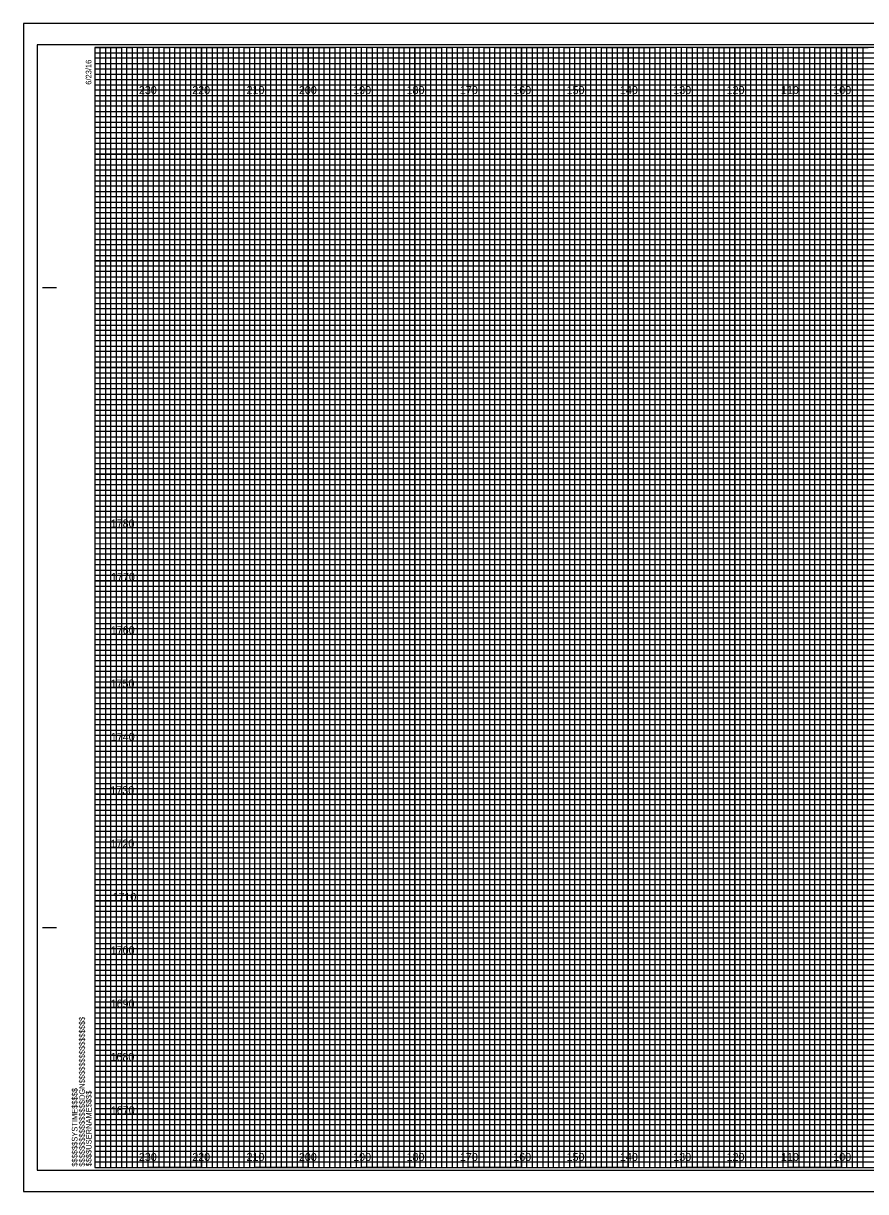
# Model space of a CAD drawing. Extents: x -419 to 4739, y -630 to 13534.
# Drawn here: x 3347.7 to 3505.6, y -29.6 to 189.4 of the extents above; entities that cross this region are included whole.
import ezdxf

# ---------------------------------------------------------------- set-up
doc = ezdxf.new("R2010")
doc.units = 0
for name, color, linetype in [('Old_Level_62', 7, 'Continuous'), ('Pattern 1', 7, 'Continuous'), ('Pattern 18', 7, 'Continuous'), ('Pattern 4', 7, 'Continuous'), ('Pattern 5', 7, 'Continuous'), ('Prop Dimension', 7, 'Continuous'), ('Prop Horizontal Alignment', 7, 'Continuous'), ('Raster_Level_0', 7, 'Continuous'), ('Scratch_Level_0', 7, 'Continuous'), ('Scratch_Level_3', 7, 'Continuous'), ('Scratch_Level_5', 7, 'Continuous')]:
    doc.layers.add(name, color=color, linetype=linetype)

msp = doc.modelspace()

# ---------------------------------------------------------------- linework, layer by layer
at = {"layer": 'Old_Level_62'}
for p, q in [((3351.3, 139.94), (3353.8, 139.94)), ((3351.4, 139.94), (3353.9, 139.94)), ((3351.3, 19.94), (3353.8, 19.94)), ((3351.4, 19.94), (3353.9, 19.94)), ((3361.1, -25.06), (3361.1, -25.06)), ((3361.1, -25.06), (3361.1, -25.06)), ((3361.1, -25.06), (3361.1, -25.06)), ((3361.1, -25.06), (3361.1, -25.06)), ((3361.1, -25.06), (3361.1, -25.06)), ((3361.1, -25.06), (3361.1, -25.06)), ((3361.1, -25.06), (3361.1, -25.06))]:
    msp.add_line(p, q, dxfattribs=at)
msp.add_lwpolyline([(3681.1, 184.94), (3361.1, 184.94), (3361.1, -25.06), (3681.1, -25.06)], close=True, dxfattribs=at)
at = {"layer": 'Pattern 18'}
msp.add_lwpolyline([(3347.7, -29.56), (3684.4, -29.56), (3684.4, 189.44), (3347.7, 189.44)], close=True, dxfattribs=at)
at = {"layer": 'Pattern 4'}
for p, q in [((3361.1, 183.94), (3621.1, 183.94)), ((3621.1, 182.92), (3361.1, 182.92)), ((3361.1, 182.92), (3361.1, 181.94)), ((3361.1, 181.94), (3621.1, 181.94)), ((3621.1, 180.83), (3361.1, 180.83)), ((3361.1, 180.83), (3361.1, 178.94)), ((3361.1, 178.94), (3681.1, 178.94))]:
    msp.add_line(p, q, dxfattribs=at)
for points in [[(3361.1, 177.94), (3631.1, 177.94), (3681.1, 177.94), (3681.1, 176.94), (3361.1, 176.94)], [(3361.1, 175.94), (3681.1, 175.94), (3681.1, 173.94), (3361.1, 173.94)], [(3361.1, 172.94), (3681.1, 172.94), (3681.1, 171.94), (3361.1, 171.92)], [(3361.1, 170.94), (3681.1, 170.94), (3681.1, 168.94), (3361.1, 168.94)], [(3361.1, 167.94), (3681.1, 167.94), (3681.1, 166.94), (3361.1, 166.94)], [(3361.1, 165.94), (3681.1, 165.94), (3681.1, 163.94), (3361.1, 163.94)], [(3361.1, 162.94), (3681.1, 162.94), (3681.1, 161.94), (3361.1, 161.94)], [(3361.1, 160.94), (3681.1, 160.94), (3681.1, 158.94), (3361.1, 158.94)], [(3361.1, 157.94), (3681.1, 157.94), (3681.1, 156.94), (3361.1, 156.94)], [(3361.1, 155.94), (3681.1, 155.94), (3681.1, 153.94), (3361.1, 153.94)], [(3361.1, 152.94), (3681.1, 152.94), (3681.1, 151.94), (3361.1, 151.94)], [(3361.1, 150.94), (3681.1, 150.94), (3681.1, 148.89), (3681.1, 147.94), (3681.1, 146.94), (3361.1, 146.94)], [(3361.1, 148.94), (3681.1, 148.94), (3681.1, 147.94), (3361.1, 147.94)], [(3361.1, 145.94), (3681.1, 145.94), (3681.1, 143.94), (3361.1, 143.97)], [(3361.1, 143.97), (3681.1, 143.94), (3681.1, 142.94), (3361.1, 142.94)], [(3361.1, 141.94), (3681.1, 141.94), (3681.1, 140.94), (3361.1, 140.94)], [(3361.1, 138.94), (3681.1, 138.94), (3681.1, 137.94), (3361.1, 137.94)], [(3361.1, 136.94), (3681.1, 136.94), (3681.1, 135.94), (3361.1, 135.94)], [(3361.03, 133.83), (3681.1, 133.83), (3681.1, 132.82), (3361.03, 132.82)], [(3361.1, 131.94), (3681.1, 131.94), (3681.1, 130.94), (3361.1, 130.94)], [(3361.1, 128.94), (3681.1, 128.94), (3681.1, 127.94), (3361.1, 127.94)], [(3361.1, 126.94), (3681.1, 126.94), (3681.1, 125.94), (3361.1, 125.94)], [(3361.1, 123.94), (3681.1, 123.94), (3681.1, 122.94), (3361.1, 122.94)], [(3361.1, 121.94), (3681.1, 121.94), (3681.1, 120.94), (3361.1, 120.94)], [(3361.1, 118.94), (3681.1, 118.94), (3681.1, 117.94), (3361.1, 117.94)], [(3361.1, 116.94), (3681.1, 116.94), (3681.1, 115.94), (3361.1, 115.94)], [(3361.1, 113.94), (3681.1, 113.94), (3681.09, 112.92), (3361.1, 112.94)], [(3361.1, 111.94), (3681.1, 111.94), (3681.1, 110.94), (3361.1, 110.94)], [(3361.1, 108.94), (3681.1, 108.94), (3681.1, 107.94), (3361.1, 107.94)], [(3361.1, 106.94), (3681.1, 106.94), (3681.1, 105.94), (3361.1, 105.94)], [(3361.1, 103.94), (3681.1, 103.94), (3681.1, 102.94), (3361.1, 102.94)], [(3361.1, 101.94), (3681.1, 101.94), (3681.1, 100.94), (3361.1, 100.94)], [(3361.1, 98.94), (3681.1, 98.94), (3681.1, 97.94), (3361.1, 97.94)], [(3361.1, 96.94), (3681.1, 96.94), (3681.1, 95.94), (3361.1, 95.94)], [(3361.1, 93.94), (3681.1, 93.94), (3681.1, 92.94), (3361.1, 92.94)], [(3361.1, 91.93), (3681.17, 91.85), (3681.1, 90.94), (3361.1, 90.94)], [(3361.1, 88.94), (3681.1, 88.94), (3681.1, 87.94), (3361.1, 87.94)], [(3361.1, 86.94), (3681.1, 86.94), (3681.1, 85.94), (3361.1, 85.94)], [(3361.1, 83.94), (3681.1, 83.94), (3681.1, 82.94), (3361.1, 82.94)], [(3361.1, 81.94), (3681.1, 81.94), (3681.1, 80.94), (3361.1, 80.94)], [(3361.1, 78.94), (3681.1, 78.94), (3681.1, 77.94), (3361.1, 77.94)], [(3361.1, 76.94), (3681.1, 76.94), (3681.1, 75.94), (3361.1, 75.94)], [(3361.1, 73.94), (3681.1, 73.94), (3681.1, 72.94), (3361.1, 72.94)], [(3361.1, 71.94), (3681.1, 71.94), (3681.1, 70.94), (3361.1, 70.94)], [(3361.1, 68.94), (3681.1, 68.94), (3681.1, 67.94), (3361.1, 67.94)], [(3361.1, 66.94), (3681.1, 66.94), (3681.1, 65.94), (3361.1, 65.94)], [(3361.1, 63.94), (3681.1, 63.94), (3681.1, 62.94), (3361.1, 62.94)], [(3361.1, 61.94), (3681.1, 61.94), (3681.1, 60.94), (3361.1, 60.94)], [(3361.1, 58.94), (3681.1, 58.94), (3681.1, 57.94), (3361.1, 57.94)], [(3361.1, 56.94), (3681.1, 56.94), (3681.1, 55.94), (3361.1, 55.94)], [(3361.1, 53.94), (3681.1, 53.94), (3681.09, 52.92), (3361.1, 52.94)], [(3361.1, 51.94), (3681.1, 51.94), (3681.1, 50.94), (3361.1, 50.94)], [(3361.1, 48.94), (3681.1, 48.94), (3681.1, 47.94), (3361.1, 47.94)], [(3361.1, 46.94), (3681.1, 46.94), (3681.1, 45.94), (3361.1, 45.94)], [(3361.1, 43.94), (3681.1, 43.94), (3681.1, 42.94), (3361.1, 42.94)], [(3361.1, 41.94), (3681.1, 41.94), (3681.1, 40.94), (3361.1, 40.94)], [(3361.1, 38.94), (3681.1, 38.94), (3681.1, 37.94), (3361.1, 37.94)], [(3361.1, 36.94), (3681.1, 36.94), (3681.1, 35.94), (3361.1, 35.94)], [(3361.1, 33.94), (3681.1, 33.94), (3681.1, 32.94), (3361.1, 32.94)], [(3361.1, 31.93), (3681.17, 31.85), (3681.1, 30.94), (3361.1, 30.94)], [(3361.1, 28.94), (3681.1, 28.94), (3681.1, 27.94), (3361.1, 27.94)], [(3361.1, 26.94), (3681.1, 26.94), (3681.1, 25.94), (3361.1, 25.94)], [(3361.1, 23.94), (3681.1, 23.94), (3681.1, 22.94), (3361.1, 22.94)], [(3361.1, 21.94), (3681.1, 21.94), (3681.1, 20.94), (3361.1, 20.94)], [(3361.1, 18.94), (3681.1, 18.94), (3681.1, 17.94), (3361.1, 17.94)], [(3361.1, 16.94), (3681.1, 16.94), (3681.1, 15.94), (3361.1, 15.94)], [(3361.1, 13.94), (3681.1, 13.94), (3681.1, 12.94), (3361.1, 12.94)], [(3361.1, 11.94), (3681.1, 11.94), (3681.1, 10.94), (3361.1, 10.94)], [(3361.1, 8.94), (3681.1, 8.94), (3681.1, 7.94), (3361.1, 7.94)], [(3361.1, 6.94), (3681.1, 6.94), (3681.1, 5.94), (3361.1, 5.94)], [(3361.1, 3.94), (3681.1, 3.94), (3681.1, 2.94), (3361.1, 2.94)], [(3361.1, 1.94), (3681.1, 1.94), (3681.1, 0.94), (3361.1, 0.94)], [(3361.1, -1.06), (3681.1, -1.06), (3681.1, -2.06), (3361.1, -2.06)], [(3361.1, -3.06), (3681.1, -3.06), (3681.1, -4.06), (3361.1, -4.06)], [(3361.1, -6.06), (3681.1, -6.06), (3681.1, -7.06), (3361.1, -7.06)], [(3361.1, -8.06), (3681.1, -8.06), (3681.1, -9.06), (3361.1, -9.06)], [(3361.1, -11.06), (3681.1, -11.06), (3681.1, -12.06), (3361.1, -12.06)], [(3361.1, -13.06), (3681.1, -13.06), (3681.1, -14.06), (3361.1, -14.06)], [(3361.1, -16.06), (3681.1, -16.06), (3681.1, -17.06), (3361.1, -17.06)], [(3361.1, -18.06), (3681.1, -18.06), (3681.1, -19.06), (3361.1, -19.06)], [(3361.1, -21.06), (3681.1, -21.06), (3681.1, -22.06), (3361.1, -22.06)], [(3361.1, -23.06), (3681.1, -23.06), (3681.1, -24.06), (3361.1, -24.06)]]:
    msp.add_lwpolyline(points, dxfattribs=at)
at = {"layer": 'Pattern 5'}
for p, q in [((3684.4, 189.44), (3347.7, 189.44)), ((3347.7, 189.44), (3347.7, -29.56)), ((3347.7, -29.56), (3684.4, -29.56))]:
    msp.add_line(p, q, dxfattribs=at)
at = {"layer": 'Prop Dimension'}
for points in [[(3361.1, -25.06), (3362.1, -25.06), (3362.1, 184.94), (3363.1, 184.94), (3363.1, -25.06)], [(3363.1, -25.06), (3364.1, -25.06), (3364.1, 184.94), (3365.1, 184.94), (3365.1, -25.06)], [(3366.1, -25.06), (3367.1, -25.06), (3367.1, 184.94), (3368.1, 184.94), (3368.1, -25.06)], [(3368.1, -25.06), (3369.1, -25.06), (3369.1, 184.94), (3370.1, 184.94), (3370.1, -25.06)], [(3371.1, -25.06), (3372.1, -25.06), (3372.1, 184.94), (3373.1, 184.94), (3373.1, -25.06)], [(3373.1, -25.06), (3374.1, -25.06), (3374.1, 184.94), (3375.1, 184.94), (3375.1, -25.06)], [(3376.1, -25.06), (3377.1, -25.06), (3377.1, 184.94), (3378.1, 184.94), (3378.1, -25.06)], [(3378.1, -25.06), (3379.1, -25.06), (3379.1, 184.94), (3380.1, 184.94), (3380.1, -25.06)], [(3381.1, -25.06), (3382.1, -25.06), (3382.1, 184.94), (3383.1, 184.94), (3383.1, -25.06)], [(3383.1, -25.06), (3384.1, -25.06), (3384.1, 184.94), (3385.1, 184.94), (3385.1, -25.06)], [(3386.1, -25.06), (3387.1, -25.06), (3387.1, 184.94), (3388.1, 184.94), (3388.1, -25.06)], [(3388.1, -25.06), (3389.1, -25.06), (3389.1, 184.94), (3390.1, 184.94), (3390.1, -25.06)], [(3391.1, -25.06), (3392.1, -25.06), (3392.1, 184.94), (3393.1, 184.94), (3393.1, -25.06)], [(3393.1, -25.06), (3394.1, -25.06), (3394.1, 184.94), (3395.1, 184.94), (3395.1, -25.06)], [(3396.1, -25.06), (3397.1, -25.06), (3397.1, 184.94), (3398.1, 184.94), (3398.1, -25.06)], [(3398.1, -25.06), (3399.1, -25.06), (3399.1, 184.94), (3400.1, 184.94), (3400.1, -25.06)], [(3401.1, -25.06), (3402.1, -25.06), (3402.1, 184.94), (3403.1, 184.94), (3403.1, -25.06)], [(3403.1, -25.06), (3404.1, -25.06), (3404.1, 184.94), (3405.1, 184.94), (3405.1, -25.06)], [(3406.1, -25.06), (3407.1, -25.06), (3407.1, 184.94), (3408.1, 184.94), (3408.1, -25.06)], [(3408.1, -25.06), (3409.1, -25.06), (3409.1, 184.94), (3410.1, 184.94), (3410.1, -25.06)], [(3411.1, -25.06), (3412.1, -25.06), (3412.1, 184.94), (3413.1, 184.94), (3413.1, -25.06)], [(3413.1, -25.06), (3414.1, -25.06), (3414.1, 184.94), (3415.1, 184.94), (3415.1, -25.06)], [(3416.1, -25.06), (3417.1, -25.06), (3417.1, 184.94), (3418.1, 184.94), (3418.1, -25.06)], [(3418.1, -25.06), (3419.1, -25.06), (3419.1, 184.94), (3420.1, 184.94), (3420.1, -25.06)], [(3421.1, -25.06), (3422.1, -25.06), (3422.1, 184.94), (3423.1, 184.94), (3423.1, -25.06)], [(3423.1, -25.06), (3424.1, -25.06), (3424.1, 184.94), (3425.1, 184.94), (3425.1, -25.06)], [(3426.1, -25.06), (3427.1, -25.06), (3427.1, 184.94), (3428.1, 184.94), (3428.1, -25.06)], [(3428.1, -25.06), (3429.1, -25.06), (3429.1, 184.94), (3430.1, 184.94), (3430.1, -25.06)], [(3431.1, -25.06), (3432.1, -25.06), (3432.1, 184.94), (3433.1, 184.94), (3433.1, -25.06)], [(3433.1, -25.06), (3434.1, -25.06), (3434.1, 184.94), (3435.1, 184.94), (3435.1, -25.06)], [(3436.1, -25.06), (3437.1, -25.06), (3437.1, 184.94), (3438.1, 184.94), (3438.1, -25.06)], [(3438.1, -25.06), (3439.1, -25.06), (3439.1, 184.94), (3440.1, 184.94), (3440.1, -25.06)], [(3441.1, -25.06), (3442.1, -25.06), (3442.1, 184.94), (3443.1, 184.94), (3443.1, -25.06)], [(3443.1, -25.06), (3444.1, -25.06), (3444.1, 184.94), (3445.1, 184.94), (3445.1, -25.06)], [(3446.1, -25.06), (3447.1, -25.06), (3447.1, 184.94), (3448.1, 184.94), (3448.1, -25.06)], [(3448.1, -25.06), (3449.1, -25.06), (3449.1, 184.94), (3450.1, 184.94), (3450.1, -25.06)], [(3451.1, -25.06), (3452.1, -25.06), (3452.1, 184.94), (3453.1, 184.94), (3453.1, -25.06)], [(3453.1, -25.06), (3454.1, -25.06), (3454.1, 184.94), (3455.1, 184.94), (3455.1, -25.06)], [(3456.1, -25.06), (3457.1, -25.06), (3457.1, 184.94), (3458.1, 184.94), (3458.1, -25.06)], [(3458.1, -25.06), (3459.1, -25.06), (3459.1, 184.94), (3460.1, 184.94), (3460.1, -25.06)], [(3461.1, -25.06), (3462.1, -25.06), (3462.1, 184.94), (3463.1, 184.94), (3463.1, -25.06)], [(3463.1, -25.06), (3464.1, -25.06), (3464.1, 184.94), (3465.1, 184.94), (3465.1, -25.06)], [(3466.1, -25.06), (3467.1, -25.06), (3467.1, 184.94), (3468.1, 184.94), (3468.1, -25.06)], [(3468.1, -25.06), (3469.1, -25.06), (3469.1, 184.94), (3470.1, 184.94), (3470.1, -25.06)], [(3471.1, -25.06), (3472.1, -25.06), (3472.1, 184.94), (3473.1, 184.94), (3473.1, -25.06)], [(3473.1, -25.06), (3474.1, -25.06), (3474.1, 184.94), (3475.1, 184.94), (3475.1, -25.06)], [(3476.1, -25.06), (3477.1, -25.06), (3477.1, 184.94), (3478.1, 184.94), (3478.1, -25.06)], [(3478.1, -25.06), (3479.1, -25.06), (3479.1, 184.94), (3480.1, 184.94), (3480.1, -25.06)], [(3481.1, -25.06), (3482.1, -25.06), (3482.1, 184.94), (3483.1, 184.94), (3483.1, -25.06)], [(3483.1, -25.06), (3484.1, -25.06), (3484.1, 184.94), (3485.1, 184.94), (3485.1, -25.06)], [(3486.1, -25.06), (3487.1, -25.06), (3487.1, 184.94), (3488.1, 184.94), (3488.1, -25.06)], [(3488.1, -25.06), (3489.1, -25.06), (3489.1, 184.94), (3490.1, 184.94), (3490.1, -25.06)], [(3491.1, -25.06), (3492.1, -25.06), (3492.1, 184.94), (3493.1, 184.94), (3493.1, -25.06)], [(3493.1, -25.06), (3494.1, -25.06), (3494.1, 184.94), (3495.1, 184.94), (3495.1, -25.06)], [(3496.1, -25.06), (3497.1, -25.06), (3497.1, 184.94), (3498.1, 184.94), (3498.1, -25.06)], [(3498.1, -25.06), (3499.1, -25.06), (3499.1, 184.94), (3500.1, 184.94), (3500.1, -25.06)], [(3501.1, -25.06), (3502.1, -25.06), (3502.1, 184.94), (3503.1, 184.94), (3503.1, -25.06)], [(3503.1, -25.06), (3504.1, -25.06), (3504.1, 184.94), (3505.1, 184.94), (3505.1, -25.06)]]:
    msp.add_lwpolyline(points, dxfattribs=at)
at = {"layer": 'Prop Horizontal Alignment'}
for points in [[(3361.1, 184.94), (3366.1, 184.94), (3366.1, -25.06), (3376.1, -25.06), (3376.1, 184.94), (3386.1, 184.94), (3386.1, -25.06), (3396.1, -25.06), (3396.1, 184.94), (3406.1, 184.94), (3406.1, -25.06), (3416.1, -25.06), (3416.1, 184.94), (3426.1, 184.94), (3426.1, -25.06), (3436.1, -25.06), (3436.1, 184.94), (3446.1, 184.94), (3446.1, -25.06), (3456.1, -25.06), (3456.1, 184.94), (3466.1, 184.94), (3466.1, -25.06), (3476.1, -25.06), (3476.1, 184.94), (3486.1, 184.94), (3486.1, -25.06), (3496.1, -25.06), (3496.1, 184.94), (3506.1, 184.94)], [(3361.1, 179.94), (3636.1, 179.94)], [(3361.1, 159.94), (3681.1, 159.94), (3681.1, 169.94), (3361.1, 169.94)], [(3361.1, 139.94), (3681.1, 139.94), (3681.1, 149.94), (3361.1, 149.94)], [(3361.1, 119.94), (3681.1, 119.94), (3681.1, 129.94), (3361.1, 129.94)], [(3361.1, 99.94), (3681.1, 99.94), (3681.1, 109.94), (3361.1, 109.94)], [(3361.1, 79.94), (3681.1, 79.94), (3681.1, 89.94), (3361.1, 89.94)], [(3361.1, 59.94), (3681.1, 59.94), (3681.1, 69.94), (3361.1, 69.94)], [(3361.1, 39.94), (3681.1, 39.94), (3681.1, 49.94), (3361.1, 49.94)], [(3361.1, 19.94), (3681.1, 19.94), (3681.1, 29.94), (3361.1, 29.94)], [(3361.1, -0.06), (3681.1, -0.06), (3681.1, 9.94), (3361.1, 9.94)], [(3361.1, -20.06), (3681.1, -20.06), (3681.1, -10.06), (3361.1, -10.06)]]:
    msp.add_lwpolyline(points, dxfattribs=at)
at = {"layer": 'Scratch_Level_0'}
for p, q in [((3371.1, -25.06), (3371.1, 184.94)), ((3381.1, -25.06), (3381.1, 184.94)), ((3391.1, -25.06), (3391.1, 184.94)), ((3401.1, -25.06), (3401.1, 184.94)), ((3411.1, -25.06), (3411.1, 184.94)), ((3421.1, -25.06), (3421.1, 184.94)), ((3431.1, -25.06), (3431.1, 184.94)), ((3441.1, -25.06), (3441.1, 184.94)), ((3451.1, -25.06), (3451.1, 184.94)), ((3461.1, -25.06), (3461.1, 184.94)), ((3471.1, -25.06), (3471.1, 184.94)), ((3481.1, -25.06), (3481.1, 184.94)), ((3491.1, -25.06), (3491.1, 184.94)), ((3501.1, -25.06), (3501.1, 184.94)), ((3361.1, 174.94), (3681.1, 174.94)), ((3361.1, 164.94), (3681.1, 164.94)), ((3361.1, 154.94), (3681.1, 154.94)), ((3361.1, 144.94), (3681.1, 144.94)), ((3361.1, 134.94), (3681.1, 134.94)), ((3361.1, 124.94), (3681.1, 124.94)), ((3361.1, 114.94), (3681.1, 114.94)), ((3361.1, 104.94), (3681.1, 104.94)), ((3361.1, 94.94), (3681.1, 94.94)), ((3361.1, 84.94), (3681.1, 84.94)), ((3361.1, 74.94), (3681.1, 74.94)), ((3361.1, 64.94), (3681.1, 64.94)), ((3361.1, 54.94), (3681.1, 54.94)), ((3361.1, 44.94), (3681.1, 44.94)), ((3361.1, 34.94), (3681.1, 34.94)), ((3361.1, 24.94), (3681.1, 24.94)), ((3361.1, 14.94), (3681.1, 14.94)), ((3361.1, 4.94), (3681.1, 4.94)), ((3361.1, -5.06), (3681.1, -5.06)), ((3361.1, -15.06), (3681.1, -15.06))]:
    msp.add_line(p, q, dxfattribs=at)
at = {"layer": 'Scratch_Level_3'}
for p, q in [((3371.1, 184.94), (3361.1, 184.94)), ((3371.1, -25.06), (3371.1, 184.94)), ((3391.1, 184.94), (3381.1, 184.94)), ((3381.1, 184.94), (3381.1, -25.06)), ((3391.1, -25.06), (3391.1, 184.94)), ((3411.1, 184.94), (3401.1, 184.94)), ((3401.1, 184.94), (3401.1, -25.06)), ((3411.1, -25.06), (3411.1, 184.94)), ((3431.1, 184.94), (3421.1, 184.94)), ((3421.1, 184.94), (3421.1, -25.06)), ((3431.1, -25.06), (3431.1, 184.94)), ((3451.1, 184.94), (3441.1, 184.94)), ((3441.1, 184.94), (3441.1, -25.06)), ((3451.1, -25.06), (3451.1, 184.94)), ((3471.1, 184.94), (3461.1, 184.94)), ((3461.1, 184.94), (3461.1, -25.06)), ((3471.1, -25.06), (3471.1, 184.94)), ((3491.1, 184.94), (3481.1, 184.94)), ((3481.1, 184.94), (3481.1, -25.06)), ((3491.1, -25.06), (3491.1, 184.94)), ((3511.1, 184.94), (3501.1, 184.94)), ((3501.1, 184.94), (3501.1, -25.06)), ((3381.1, -25.06), (3371.1, -25.06)), ((3401.1, -25.06), (3391.1, -25.06)), ((3421.1, -25.06), (3411.1, -25.06)), ((3441.1, -25.06), (3431.1, -25.06)), ((3461.1, -25.06), (3451.1, -25.06)), ((3481.1, -25.06), (3471.1, -25.06)), ((3501.1, -25.06), (3491.1, -25.06))]:
    msp.add_line(p, q, dxfattribs=at)
for points in [[(3361.1, 174.94), (3681.1, 174.94), (3681.1, 164.94), (3361.1, 164.94)], [(3361.1, 154.94), (3681.1, 154.94), (3681.1, 144.94), (3361.1, 144.94)], [(3361.1, 134.94), (3681.1, 134.94), (3681.1, 124.94), (3361.1, 124.94)], [(3361.1, 114.94), (3681.1, 114.94), (3681.1, 104.94), (3361.1, 104.94)], [(3361.1, 94.94), (3681.1, 94.94), (3681.1, 84.94), (3361.1, 84.94)], [(3361.1, 74.94), (3681.1, 74.94), (3681.1, 64.94), (3361.1, 64.94)], [(3361.1, 54.94), (3681.1, 54.94), (3681.1, 44.94), (3361.1, 44.94)], [(3361.1, 34.94), (3681.1, 34.94), (3681.1, 24.94), (3361.1, 24.94)], [(3361.1, 14.94), (3681.1, 14.94), (3681.1, 4.94), (3361.1, 4.94)], [(3361.1, -5.06), (3681.1, -5.06), (3681.1, -15.06), (3361.1, -15.06)]]:
    msp.add_lwpolyline(points, dxfattribs=at)
at = {"layer": 'Scratch_Level_5'}
msp.add_lwpolyline([(3350.3, -25.56), (3683.5, -25.56), (3683.5, 185.44), (3350.3, 185.44)], close=True, dxfattribs=at)

# ---------------------------------------------------------------- texts
at = {"layer": 'Old_Level_62'}
for s, p in [('6/23/16', (3360.45, 177.94)), ('$$$$$$$$$$$$$$$$DGN$$$$$$$$$$$$$$$$', (3359.22, -24.88)), ('$$$$$$SYSTIME$$$$$', (3357.84, -24.88)), ('$$$$USERNAME$$$$', (3360.48, -24.83))]:
    msp.add_text(s, height=1.05, rotation=90, dxfattribs=at).set_placement(p)
at = {"layer": 'Pattern 1'}
for s, p in [('1780', (3364.08, 94.94)), ('1770', (3364.14, 84.94)), ('1760', (3364.1, 74.94)), ('1750', (3364.06, 64.94)), ('1740', (3364.1, 54.94)), ('1730', (3364.02, 44.94)), ('1720', (3364.03, 34.94)), ('1710', (3364.41, 24.94)), ('1700', (3364.08, 14.94)), ('1690', (3364.07, 4.94)), ('1680', (3364.04, -5.06)), ('1670', (3364.1, -15.06))]:
    msp.add_text(s, height=1.5, dxfattribs=at).set_placement(p)
at = {"layer": 'Raster_Level_0'}
for s, p in [('230', (3369.36, 176.19)), ('220', (3379.36, 176.19)), ('210', (3389.54, 176.19)), ('200', (3399.36, 176.19)), ('190', (3409.54, 176.19)), ('180', (3419.54, 176.19)), ('170', (3429.54, 176.19)), ('160', (3439.54, 176.19)), ('150', (3449.54, 176.19)), ('140', (3459.54, 176.19)), ('130', (3469.54, 176.19)), ('120', (3479.54, 176.19)), ('110', (3489.72, 176.19)), ('100', (3499.54, 176.19)), ('230', (3369.36, -23.81)), ('220', (3379.36, -23.81)), ('210', (3389.54, -23.81)), ('200', (3399.36, -23.81)), ('190', (3409.54, -23.81)), ('180', (3419.54, -23.81)), ('170', (3429.54, -23.81)), ('160', (3439.54, -23.81)), ('150', (3449.54, -23.81)), ('140', (3459.54, -23.81)), ('130', (3469.54, -23.81)), ('120', (3479.54, -23.81)), ('110', (3489.72, -23.81)), ('100', (3499.54, -23.81))]:
    msp.add_text(s, height=1.5, dxfattribs=at).set_placement(p)

doc.saveas('drawing.dxf')
